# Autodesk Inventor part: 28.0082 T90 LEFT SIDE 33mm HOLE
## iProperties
Created: 2007-04
Part Number: 28.0082 T90 LEFT SIDE 33mm HOLE
Document SubType Name: Modeling
Designer: Andy Moles
Material: Aluminum-6061
Density: 2.71 g/cm^3
Author: Andy Moles
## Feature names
1. Extrusion1
2. Chamfer1
3. Hole1
4. Hole2
5. Hole3
6. Hole4
7. Hole5
8. Extrusion2
9. Extrusion3
10. Hole6
11. Extrusion4
12. Mirror1
13. Hole7
14. Hole8
15. Hole9
16. Hole10
